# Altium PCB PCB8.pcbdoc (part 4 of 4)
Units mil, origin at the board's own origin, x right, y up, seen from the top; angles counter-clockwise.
Board outline 6799.06 x 5716.8 mil, 2 copper layers (Top Layer, Bottom Layer); 312 components, 374 nets, 1333 pads, 994 vias.
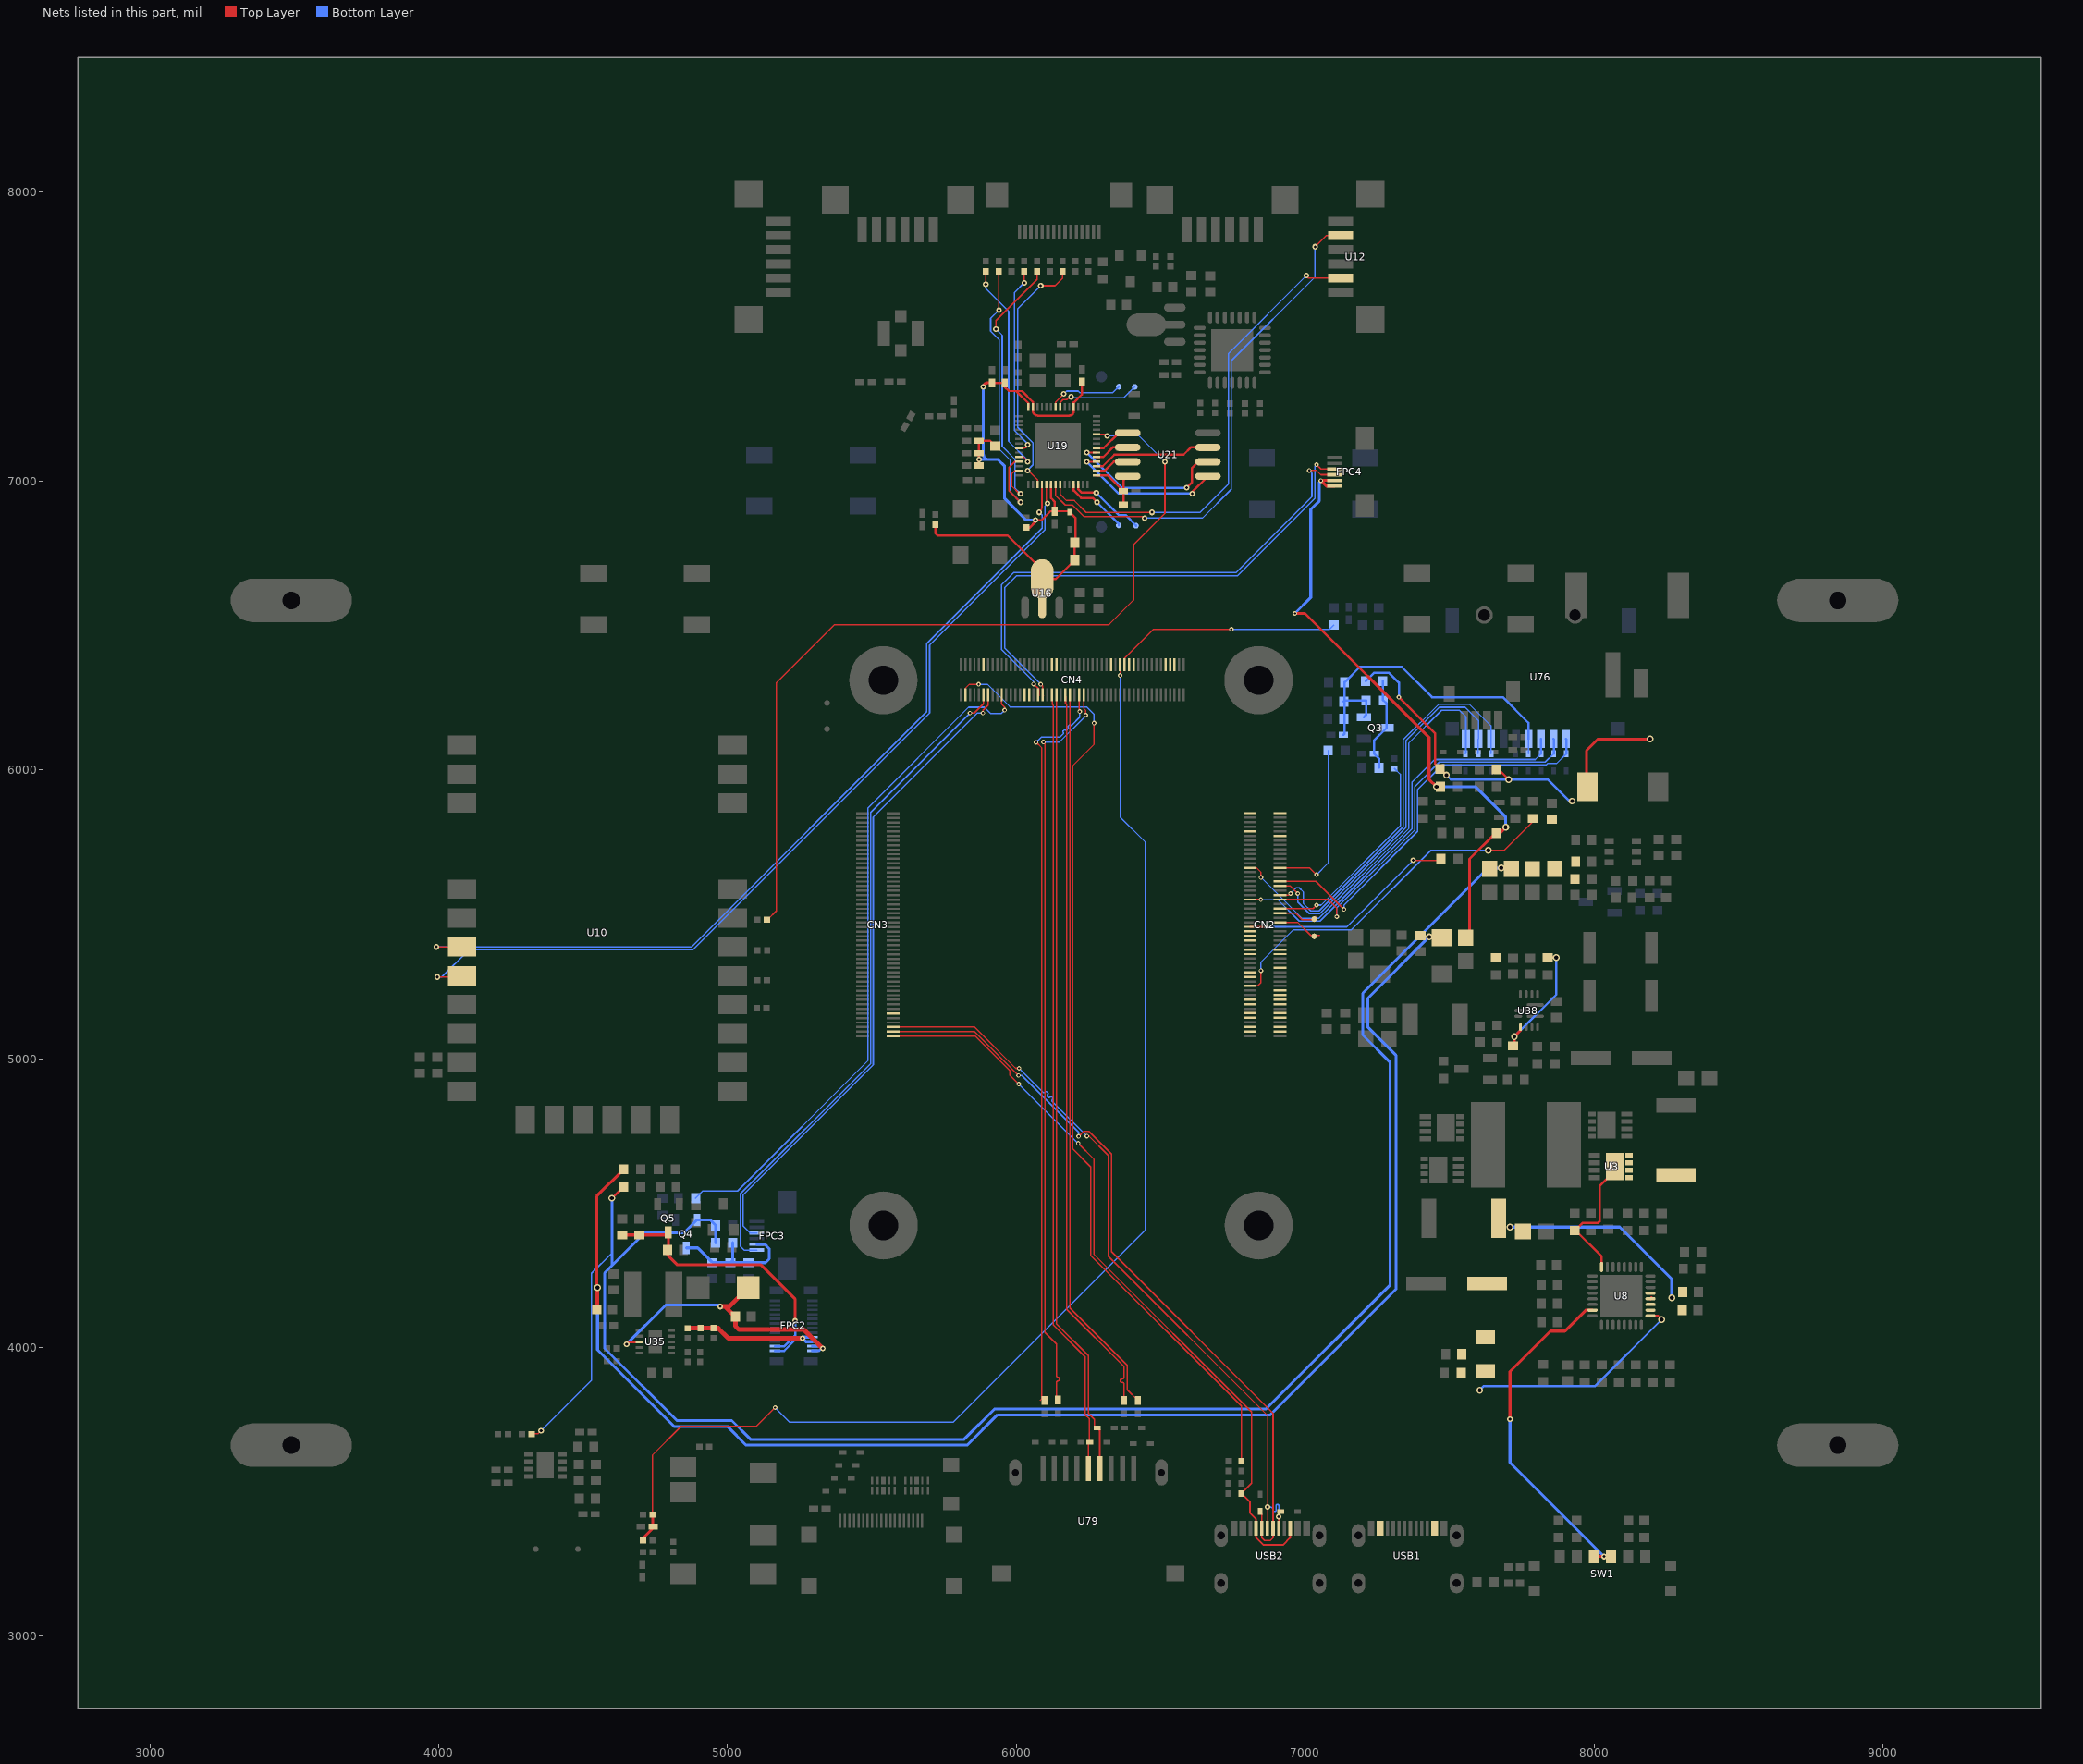
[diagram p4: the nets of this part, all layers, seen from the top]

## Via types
v1: diameter 19.7, hole 9.84, Top Layer to Bottom Layer, 526 vias
v2: diameter 15.75, hole 7.87, Top Layer to Bottom Layer, 322 vias
v3: diameter 19.68, hole 9.84, Top Layer to Bottom Layer, 98 vias
v4: diameter 23.62, hole 13.78, Top Layer to Bottom Layer, 39 vias
v5: diameter 24, hole 12, Top Layer to Bottom Layer, 9 vias

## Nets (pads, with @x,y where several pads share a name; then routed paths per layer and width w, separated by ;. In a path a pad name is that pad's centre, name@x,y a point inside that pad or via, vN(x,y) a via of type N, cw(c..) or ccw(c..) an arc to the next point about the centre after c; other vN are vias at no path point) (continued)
PCON: R8.2 R375.1 U3.5 U3.6 U3.7 U3.8 U8.16 | length 475.5
  Top Layer w7.87: R8.2@7933.02,4405.21 R8.2@7935.75,4405.21 ; U8.16@8026.6,4278.49 8026.6,4314.37 R8.2@7935.75,4405.21 ; U3.8@8072.36,4626.32 8072.36,4611.16 8019.47,4558.27 8019.47,4436.49 8014.47,4431.49 7962.03,4431.49 R8.2@7935.75,4405.21
PHY1_LED0_Y1: CN2.19
PHY1_LED1_G: CN2.17
PHY1_LED2_Y: CN2.15
PHY1_MDI0+: CN2.12
PHY1_MDI0-: CN2.10
PHY1_MDI1+: CN2.4
PHY1_MDI1-: CN2.6
PHY1_MDI2+: CN2.11
PHY1_MDI2-: CN2.9
PHY1_MDI3+: CN2.3
PHY1_MDI3-: CN2.5
PI_NLED_ACTIVITY: CN2.21
PMIC_RESET_KEY: CN2.100
PMW0_M0: CN2.48
PMW0_M1: CN2.50 R106.2 | length 758.5
  Top Layer w5: CN2.50@6808.76,5456.26 v2(6864.47,5456.26) ; v3(7374.47,5686.49) 7464.81,5686.49 R106.2@7469.81,5691.49
  Bottom Layer w5: v2(6864.47,5456.26) 7144.23,5456.26 v3(7374.47,5686.49)
PMW4: CN2.46
PWM3_IR: CN2.24 R97.2 | length 1245.8
  Top Layer w5: CN2.24@6820.57,5252.25 6836.48,5252.25 6847.22,5262.99 v2(6847.22,5304.33) ; v4@7644.47,5721.49 7689.47,5721.49 7787.76,5819.78 R97.2@7787.76,5831.54
  Bottom Layer w5: v2(6847.22,5304.33) 6847.22,5334.24 6958.19,5445.21 7159.13,5445.21 7435.41,5721.49 v4(7634.47,5721.49)
PWM11: CN2.31
PWRON_KEY: CN2.99
RBAT: SW1.3 SW1.4 U8.23 | length 1208.5
  Top Layer w10: v1(7709.47,3751.49) 7709.47,3916.49 7849.47,4056.49 7899.47,4056.49 7971.87,4128.89 U8.23@7995.1,4128.89 ; SW1.3@7999.94,3275.55 v1(8035.08,3275.55) SW1.4@8059,3275.55
  Bottom Layer w10: v1(7709.47,3751.49) 7709.47,3601.16 v1(8035.08,3275.55)
RST1: R36.2 U19.13 | length 978.1
  Top Layer w5: v3(5929.47,7526.49) 5929.47,7555.55 6071.73,7697.81 R36.2@6071.73,7726.46 ; U19.13@6009.66,7035.53 5994.07,7035.53 5984.47,7025.93 5984.47,6981.49 6009.47,6956.49 v3(6014.47,6956.49)
  Bottom Layer w5: v3(5929.47,7526.49) 5951.14,7504.82 5951.14,7119.82 5994.47,7076.49 5994.47,6976.49 v3(6014.47,6956.49)
RUN_PG: CN2.92
RX: U12.2 U19.22 | length 1640.6
  Top Layer w5: U19.22@6151.69,6987.99 6151.69,6954.27 6173.72,6932.24 6200.76,6932.24 6241.51,6891.49 v3(6469.47,6891.49) ; v3(7004.47,7711.49) ccw(c7013.29,7711.49) 7013.29,7702.67 U12.2@7123.29,7702.67
  Bottom Layer w5: v3(6469.47,6891.49) 6636.18,6891.49 6734.47,6989.78 6734.47,7441.49 v3(7004.47,7711.49)
RXEN: U10.6 U19.18 | length 3064.2
  Top Layer w5: v3(3992.29,5386.75) 4056.56,5386.75 ccw(c4056.56,5390.37) U10.6@4060.18,5390.37 ; v3(6079.47,6891.49) ccw(c6060.26,6914.06) 6088.7,6905.72 U19.18@6088.7,6987.99
  Bottom Layer w5: v3(3992.29,5386.75) 4875.22,5386.75 5689.47,6200.99 5689.47,6436.49 6089.47,6836.49 6089.47,6881.49 v3(6079.47,6891.49)
RY: U12.5 U19.21 | length 1785.5
  Top Layer w5: U19.21@6135.94,6987.99 6135.94,6950.02 6169.47,6916.49 6194.5,6916.49 6234.2,6876.79 6439.17,6876.79 v3(6444.47,6871.49) ; v3(7034.47,7811.49) 7073.28,7850.31 U12.5@7123.29,7850.31
  Bottom Layer w5: v3(6444.47,6871.49) 6644.47,6871.49 6744.47,6971.49 6744.47,7416.49 7034.47,7706.49 v3(7034.47,7811.49)
SARADC_IN3: CN2.37
SARADC_VIN0_KEY/RECOVERY: CN4.26
SARADC_VIN1_HW_ID: CN4.28 R100.2 | length 797.1
  Top Layer w5: CN4.28@6374.47,6361.92 CN4.28@6374.47,6363.3 ; CN4.28@6374.7,6363.54 CN4.28@6374.47,6363.3 ; v2(6744.47,6486.49) 6474.47,6486.49 6374.47,6386.49 CN4.28@6374.47,6363.3
  Bottom Layer w5: v2(6744.47,6486.49) 7084.37,6486.49 R100.2@7099.14,6501.27
SARADC_VIN2_HP_HOOK: C46.2 CN4.30 R54.2 R56.2 | length 4374.3
  Top Layer w5: R56.2@4739.47,3421.49 4739.47,3626.49 4839.47,3726.49 5099.47,3726.49 v2(5164.47,3791.49) ; CN4.30@6358.96,6363.54 6359.47,6363.03 v2(6359.47,6326.49)
  Top Layer w10: R54.2@4707.43,3331.49 4707.43,3339.45 4741.51,3373.53 R56.2@4741.51,3421.49
  Bottom Layer w5: v2(5164.47,3791.49) 5214.47,3741.49 5781.45,3741.49 6446.91,4406.94 6446.91,5749.06 6359.47,5836.49 v2(6359.47,6326.49)
SCK: R27.2 U19.38 | length 2989.9
  Top Layer w5: R27.2@5136.51,5481.49 5139.47,5481.49 5169.47,5511.49 5169.47,6301.49 5370.96,6502.98 6320.96,6502.98 6405.58,6587.6 6405.58,6779 6514.47,6887.89 v3(6514.47,7066.49) ; U19.38@6277.97,7161.52 6309.44,7161.52 v3(6314.47,7156.49)
  Bottom Layer w5: v3(6314.47,7156.49) 6424.47,7156.49 v3(6514.47,7066.49)
SCL: R30.2 U19.10 | length 757.6
  Top Layer w5: v3(5894.23,7681.49) R30.2@5894.23,7726.46 ; U19.10@6009.66,7082.78 6025.94,7082.78 6038.65,7070.08 v3(6038.65,7066.49)
  Bottom Layer w5: v3(5894.23,7681.49) 5894.23,7666.73 5973.51,7587.45 5973.51,7137.12 6038.65,7071.99 v3(6038.65,7066.49)
SCLK1: R39.2 U19.17 | length 878.4
  Top Layer w5: v3(6038.55,7036.49) 6041.54,7036.49 6072.95,7005.08 U19.17@6072.95,6987.99 ; v3(6084.47,7676.49) 6134.47,7676.49 6160.48,7702.5 R39.2@6160.48,7726.46
  Bottom Layer w5: v3(6038.55,7036.49) 6057.81,7055.76 6057.81,7132.35 6004.56,7185.6 6004.56,7596.59 v3(6084.47,7676.49)
SDA: R31.2 U19.11 | length 1035.1
  Top Layer w5: R31.2@5938.6,7726.46 5939.47,7725.59 v3(5939.47,7591.49) ; U19.11@6009.66,7067.03 5995.01,7067.03 5974.47,7046.49 5974.47,6966.49 v3(6014.47,6926.49)
  Bottom Layer w5: v3(5939.47,7591.49) 5911.13,7563.15 5911.13,7518.89 5940,7490.03 5940,7110.97 5979.47,7071.49 5979.47,6961.49 v3(6014.47,6926.49)
SDMMC0_CLK: CN2.57 R59.1 | length 741.6
  Top Layer w5: CN2.57@6913.48,5519.25 7027.22,5519.25 v2(7039.47,5531.49)
  Bottom Layer w5: v2(7039.47,5531.49) 7055.21,5531.49 7329.47,5805.75 7329.47,5984.45 R59.1@7309.47,6004.45
SDMMC0_CMD: CN2.62 D22.2 U76.3 | length 1424.8
  Top Layer w5: CN2.62@6808.76,5550.74 6846.42,5550.74 v2(6846.59,5550.58)
  Bottom Layer w5: v2(6846.59,5550.58) 6905.39,5550.58 6979.47,5476.49 7051.32,5476.49 7369.47,5794.64 7369.47,5956.49 7448.68,6035.71 7796.66,6035.71 D22.2@7816.97,6056.02
  Bottom Layer w8: U76.3@7816.43,6106.77 7816.43,6056.55 D22.2@7816.97,6056.02
SDMMC0_D0: CN2.63 D19.2 U76.7 | length 1397
  Top Layer w5: CN2.63@6913.48,5566.49 6944.47,5566.49 v2(6949.47,5571.49)
  Bottom Layer w5: v2(6949.47,5571.49) 6969.47,5591.49 6979.47,5591.49 6994.47,5576.49 6994.47,5536.49 7019.47,5511.49 7047.94,5511.49 7339.47,5803.02 7339.47,6104.22 7461.74,6226.49 7569.47,6226.49 7643.21,6152.75 U76.7@7643.21,6106.77 7644.47,6105.51 D19.2@7644.47,6056.02
SDMMC0_D1: CN2.67 D18.2 U76.8 | length 1350.6
  Top Layer w5: CN2.67@6913.48,5597.99 6947.97,5597.99 v2(6974.47,5571.49)
  Bottom Layer w5: v2(6974.47,5571.49) 6974.47,5541.49 7014.47,5501.49 7050.67,5501.49 7349.47,5800.29 7349.47,6101.49 7464.47,6216.49 7554.47,6216.49 7599.89,6171.07 U76.8@7599.89,6106.77 7599.47,6106.34 D18.2@7599.47,6056.02
SDMMC0_D2/ARMJTAG_TCK: CN2.69 D24.2 U76.1 | length 1400
  Top Layer w5: CN2.69@6913.48,5613.74 7037.22,5613.74 v2(7134.47,5516.49)
  Bottom Layer w5: v2(7134.47,5516.49) 7134.47,5531.49 7389.47,5786.49 7389.47,5931.49 7475.45,6017.48 7819.04,6017.48 7819.25,6017.26 7819.47,6017.48 7834.93,6017.48 7838.94,6021.49 7869.94,6021.49 D24.2@7904.47,6056.02
  Bottom Layer w8: U76.1@7903.04,6106.77 7904.47,6105.34 D24.2@7904.47,6056.02
SDMMC0_D3/ARMJTAG_TMS: CN2.61 D23.2 U76.2 | length 1379.8
  Top Layer w5: CN2.61@6913.48,5550.74 7080.22,5550.74 7109.47,5521.49 v2(7109.47,5491.49)
  Bottom Layer w5: v2(7109.47,5491.49) 7109.47,5521.49 7380.33,5792.35 7380.33,5942.35 7464.47,6026.49 7831.19,6026.49 D23.2@7860.72,6056.02
  Bottom Layer w8: U76.2@7859.74,6106.77 7860.72,6105.79 D23.2@7860.72,6056.02
SDMMC0_DET_L: CN2.76 D17.2 U76.CD | length 1440.6
  Top Layer w5: CN2.76@6808.76,5660.98 6831.41,5660.98 6847.14,5645.25 v2(6847.14,5627.28)
  Bottom Layer w5: v2(6847.14,5627.28) 6987.92,5486.49 7048.6,5486.49 7359.47,5797.37 7359.47,6093.21 7472.75,6206.49 7534.47,6206.49 7556.59,6184.37 U76.CD@7556.59,6106.77 7556.59,6058.14 D17.2@7554.47,6056.02
SDMMC_PWREN: CN2.75 R63.1 | length 582.8
  Top Layer w5: CN2.75@6913.48,5660.98 7014.98,5660.98 v2(7039.47,5636.49)
  Bottom Layer w5: v2(7039.47,5636.49) 7079.81,5676.83 R63.1@7079.81,6066.49
SPI0_CSO_MO: CN2.28
SPI0_MISO_MO: CN2.30
SPI3_CLK_M0: CN2.38
SPI3_CSO_M0: CN2.39
SPI3_MISO_M0: CN2.40
SPI3_MOSI_M0: CN2.44
SPICLK: U19.33 U21.6 | length 122.7
  Top Layer w7.87: U19.33@6277.97,7082.78 6300.76,7082.78 6335.42,7117.44 U21.6@6386.29,7117.44
SPICS0: U19.32 U21.1 | length 527.9
  Top Layer w7.9: v3(6244.47,7066.49) 6277.43,7066.49 U19.32@6277.97,7067.03 ; v3(6609.47,6956.49) 6609.47,6962.67 U21.1@6664.25,7017.44
  Bottom Layer w7.9: v3(6244.47,7066.49) 6354.47,6956.49 v3(6609.47,6956.49)
SPID: U19.35 U21.5 | length 130.3
  Top Layer w7.87: U19.35@6277.97,7114.27 6302.25,7114.27 6355.42,7167.44 U21.5@6386.29,7167.44
SPIHD: U19.30 U21.7 | length 121.5
  Top Layer w7.87: U19.30@6277.97,7035.53 6306.15,7035.53 6338.06,7067.44 U21.7@6386.29,7067.44
SPIQ: U19.34 U21.2 | length 570.8
  Top Layer w7.9: v3(6244.47,7098.53) U19.34@6277.97,7098.53 ; v3(6589.47,6976.49) 6608.51,6995.54 6608.51,7045.54 6630.42,7067.44 U21.2@6664.25,7067.44
  Bottom Layer w7.9: v3(6244.47,7098.53) 6366.51,6976.49 v3(6589.47,6976.49)
SPIWP: U19.31 U21.3 | length 413.7
  Top Layer w7.87: U19.31@6277.97,7051.28 6299.26,7051.28 6339.47,7091.49 6579.47,7091.49 6604.47,7116.49 6663.29,7116.49 U21.3@6664.25,7117.44
SPKN_OUT: CN4.58
SPKP_OUT: CN4.60
SYNC_IN: CN2.16
SYNC_OUT: CN2.18
TOUCH_RST: R35.2 U19.8 | length 669.3
  Top Layer w5: U19.8@6009.66,7114.27 6027.25,7114.27 ccw(c6027.88,7125.04) v3(6038.65,7125.57) ; v3(6027.35,7686.49) R35.2@6027.35,7726.46
  Bottom Layer w5: v3(6027.35,7686.49) 5993.48,7652.62 5993.48,7175.28 6038.65,7130.11 v3(6038.65,7125.57)
TP_DET_1: CN4.81 R64.2 | length 2350.9
  Top Layer w5: CN4.81@5949.15,6252.44 5949.15,6226.81 5959.47,6216.49 v2(5959.47,6206.49)
  Bottom Layer w5: R64.2@4889.13,4516.49 4914.13,4541.49 5034.47,4541.49 5486.47,4993.49 5486.47,5868.49 5834.47,6216.49 5889.47,6216.49 5910.84,6195.12 5948.09,6195.12 v2(5959.47,6206.49)
TP_INT_1: CN4.87 FPC3.3 | length 2253.3
  Top Layer w5: v2(5884.47,6196.49) 5884.47,6206.49 5901.9,6223.93 CN4.87@5901.9,6252.44
  Bottom Layer w5: FPC3.3@5101.74,4396.26 5077.9,4396.26 5053.47,4420.69 5053.47,4527.76 5504.47,4978.76 5504.47,5836.49 5864.47,6196.49 v2(5884.47,6196.49)
TP_INT_L: CN4.8
TP_PWR_DET: CN4.24
TP_RST_1: CN4.89 FPC3.6 | length 2322.3
  Top Layer w5: v2(5839.47,6196.49) 5854.47,6196.49 5886.16,6228.18 CN4.89@5886.16,6252.44
  Bottom Layer w5: FPC3.6@5101.74,4337.2 5057.44,4337.2 5044.47,4350.17 5044.47,4531.49 5495.47,4982.49 5495.47,5852.49 v2(5839.47,6196.49)
TP_RST_L: CN4.6
TS: CN4.90
TV_OUT: CN3.11
TXEN: U10.7 U19.19 | length 3120.7
  Top Layer w5: v3@3997.48,5282.58 4068.48,5282.58 ccw(c4068.48,5285.17) U10.7@4071.07,5285.17 ; U19.19@6104.45,6987.99 6104.47,6926.39 v3(6108.34,6922.52)
  Bottom Layer w5: v3(3994.89,5282.58) 4010.56,5282.58 4104.47,5376.49 4879.47,5376.49 5699.72,6196.75 5699.72,6432.25 6099.72,6832.25 6099.72,6913.9 v3(6108.34,6922.52)
U0RX: RX.1 U19.50 | length 262
  Top Layer w5: U19.50@6135.94,7256.3 6135.94,7272.96 v3(6164.47,7301.49)
  Bottom Layer w5: v3(6164.47,7301.49) 6174.47,7311.49 6214.47,7311.49 6219.47,7306.49 6334.66,7306.49 RX.1@6354.84,7326.67
U0TX: TX.1 U19.49 | length 298.4
  Top Layer w5: U19.49@6151.69,7256.3 6151.69,7271.63 6161.55,7281.49 6174.47,7281.49 6181.59,7288.62 6186.59,7288.62 v3(6189.47,7291.49)
  Bottom Layer w5: v3(6189.47,7291.49) 6192.34,7288.62 6372.42,7288.62 TX.1@6409.84,7326.04
UART2_RX: CN2.51 TP3.1 | length 159.1
  Top Layer w5: CN2.51@6913.48,5472 6973.96,5472 7019.47,5426.49 TP3.1@7039.48,5426.49 ; TP3.1@7036.48,5423.49 TP3.1@7039.48,5426.49 ; 7049.48,5426.49 TP3.1@7039.48,5426.49
UART2_TX: CN2.55 TP4.1 | length 136.8
  Top Layer w5: CN2.55@6913.48,5503.5 6967.46,5503.5 6989.47,5481.49 7025.11,5481.49 7036.48,5492.86
USB2.0_HUB_PWR: CN4.34
USB2_HOST2_DM: CN4.65 FPC4.3 | length 1829.1
  Top Layer w5: v2(6059.47,6296.93) 6060.88,6296.93 6077.97,6279.84 CN4.65@6077.97,6255.27 ; v2(7014.47,7036.49) 7039.47,7036.49 7054.23,7021.73 FPC4.3@7101.74,7021.73
  Bottom Layer w5: v2(6059.47,6296.93) 6059.47,6305.94 5948.48,6416.92 5948.48,6640.51 5990.47,6682.49 6760.47,6682.49 7023.47,6945.49 7023.47,7027.49 v2(7014.47,7036.49)
USB2_HOST2_DP: CN4.63 FPC4.4 | length 1821.1
  Top Layer w5: v2(6084.47,6296.49) 6091.35,6289.61 6091.35,6257.64 CN4.63@6093.72,6255.27 ; v2(7039.47,7056.49) 7054.54,7041.42 FPC4.4@7101.74,7041.42
  Bottom Layer w5: v2(6084.47,6296.49) 5959.47,6421.49 5959.47,6631.49 5999.47,6671.49 6765,6671.49 7034.45,6940.94 7034.45,7051.48 v2(7039.47,7056.49)
USB2_HOST3_DM: CN4.71
USB2_HOST3_DP: CN4.69
USB3_HOST1_DM: CN4.47 L6.1 | length 2569.8
  Top Layer w5: v2(6068.47,6095.4) 6088.47,6075.41 6088.47,3822.18 6083.07,3816.78 ; CN4.47@6217.22,6259.6 6217.22,6203.74 v2(6219.47,6201.49)
  Bottom Layer w5: v2(6068.47,6095.4) 6085.93,6112.87 6150.29,6112.87 6162.27,6124.85 ccw(c6159.91,6127.21) 6162.27,6129.57 cw(c6164.63,6131.93) 6162.27,6134.29 6166.03,6138.05 cw(c6168.39,6135.69) 6170.75,6138.05 ccw(c6173.11,6140.42) 6175.47,6138.05 6179.24,6141.82 ccw(c6176.88,6144.18) 6179.24,6146.54 cw(c6181.6,6148.9) 6179.24,6151.26 6183,6155.02 cw(c6185.36,6152.66) 6187.72,6155.02 ; 6187.72,6155.03 ccw(c6190.08,6157.39) 6192.45,6155.03 ; 6192.45,6155.02 6219.47,6182.05 v2(6219.47,6201.49)
USB3_HOST1_DP: CN4.45 L7.1 | length 2568.4
  Top Layer w5: v2(6093.86,6096.3) 6099.47,6090.69 6099.47,4051.54 6139.47,4011.54 6139.47,3901.25 ccw(c6144.47,3901.25) 6144.47,3896.25 cw(c6144.47,3891.25) 6149.47,3891.25 6149.47,3889.25 cw(c6144.47,3889.25) 6144.47,3884.25 ccw(c6144.47,3879.25) 6139.47,3879.25 L7.1@6139.47,3817.95 ; CN4.45@6232.97,6259.6 6232.97,6212.99 6240.52,6205.44 v2(6240.52,6189.33)
  Bottom Layer w5: v2(6093.86,6096.3) 6149.53,6096.3 6240.52,6187.28 v2(6240.52,6189.33)
USB3_HOST1_SSRXN: CN4.59 D8.2 U79.5 | length 2734.1
  Top Layer w5: CN4.59@6125.19,6255.25 6125.19,6225.77 6128.47,6222.49 6128.47,4076.94 6238.47,3966.94 6238.47,3847.94 ; 6238.06,3848.35 6238.47,3847.94 ; U79.5@6249.47,3581.1 6249.47,3666.02 D8.2@6254.47,3671.02 ; D8.2@6253.47,3672.13 D8.2@6253.47,3672.97 ; D8.2@6254.94,3671.49 D8.2@6253.47,3672.97 ; D8.2@6255.26,3671.49 D8.2@6253.47,3673.28 ; 6238.47,3847.94 6238.47,3766.94 6253.47,3751.94 D8.2@6253.47,3673.28 ; D8.2@6253.47,3672.97 D8.2@6253.47,3673.28
  Top Layer w7.87: D8.2@6254.47,3671.02 D8.2@6254.94,3671.49
USB3_HOST1_SSRXP: CN4.57 D9.2 U79.6 | length 2733.2
  Top Layer w5: CN4.57@6139.47,6255.27 6139.47,4081.49 6249.47,3971.49 6249.47,3771.49 6270.28,3750.68 D9.2@6270.28,3721.16 ; D9.2@6280.28,3720.33 D9.2@6280.28,3721.16 ; U79.6@6288.84,3581.1 6288.84,3712.6
  Top Layer w7.87: D9.2@6279.94,3721.49 6280.28,3721.16 6288.84,3712.6
USB3_HOST1_SSTXN: C49.1 CN4.53 | length 2536.8
  Top Layer w5: CN4.53@6171.15,6253.4 6170.37,6252.61 6170.37,6230.6 6174.73,6226.23 6174.73,4131.57 6372.65,3933.65 6372.65,3896.83 cw(c6366.65,3896.83) 6366.65,3890.83 6365.47,3890.83 ccw(c6365.47,3884.83) 6365.47,3878.83 6366.65,3878.83 cw(c6366.65,3872.83) 6372.65,3872.83 C49.1@6372.65,3816.78
USB3_HOST1_SSTXP: C50.1 CN4.51 | length 2540
  Top Layer w5: CN4.51@6185.73,6259.6 6185.73,4136.13 6383.65,3938.21 6383.65,3853.49 C50.1@6420.36,3816.78
USB_D+: D+.1 U19.26 | length 269.1
  Top Layer w7.87: U19.26@6214.68,6987.99 6214.68,6970.96 6225.93,6959.72 v3(6276.96,6959.72)
  Bottom Layer w7.87: v3(6276.96,6959.72) 6355.65,6881.04 6379.44,6881.04 6414.21,6846.26 D+.1@6414.21,6845.41
USB_D-: D-.1 U19.25 | length 229.4
  Top Layer w7.87: U19.25@6198.94,6987.99 6198.94,6967.02 6224.47,6941.49 6264.47,6941.49 v3(6279.47,6926.49)
  Bottom Layer w7.87: v3(6279.47,6926.49) 6354.47,6851.49 D-.1@6354.47,6846.49
USB_OTG0_DM: CN3.3 D5.2 USB2.A7 USB2.B7 | length 2655.1
  Top Layer w5: CN3.3@5572.93,5093.66 5855.03,5093.66 v2(6007.2,4941.49) ; v2(6215.74,4730.59) 6233.01,4747.87 6251.25,4747.87 6329.47,4669.65 6329.47,4331.49 6889.11,3771.86 USB2.A7@6889.11,3373.98 6889.11,3341.13 6879.47,3331.49 6859.47,3331.49 6849.74,3341.23 USB2.B7@6849.74,3373.98 6849.74,3425.75 D5.2@6843.99,3431.49
  Bottom Layer w5: v2(6007.2,4941.49) 6018.91,4941.49 6215.74,4744.66 v2(6215.74,4730.59)
USB_OTG0_DP: CN3.5 D4.2 USB2.A6 USB2.B6 | length 2648.8
  Top Layer w5: CN3.5@5572.93,5109.41 5854.84,5109.41 5997.75,4966.49 v2(6009.47,4966.49) ; v2(6244.47,4731.49) 6252.07,4731.49 6318.47,4665.09 6318.47,4315.5 6870.02,3763.95 v3(6870.02,3447.76) 6870.02,3374.57 USB2.A6@6869.43,3373.98 ; USB2.B6@6908.8,3373.98 v3(6908.75,3413.27) 6908.8,3430.34 D4.2@6914.94,3436.49
  Bottom Layer w5: v2(6009.47,4966.49) 6092.16,4883.8 ccw(c6095.91,4887.55) 6099.66,4883.8 cw(c6103.41,4880.05) 6107.16,4883.8 6108.15,4882.81 cw(c6104.4,4879.06) 6108.15,4875.31 ccw(c6111.9,4871.56) 6108.15,4867.81 6109.13,4866.83 ccw(c6112.88,4870.58) 6116.63,4866.83 cw(c6120.38,4863.08) 6124.13,4866.83 6125.12,4865.84 cw(c6121.37,4862.09) 6125.12,4858.34 ccw(c6128.87,4854.59) 6125.12,4850.84 v2(6244.47,4731.49) ; v3(6870.02,3447.76) 6878.2,3447.76 cw(c6878.2,3436.49) 6889.47,3436.49 ccw(c6894.47,3436.49) 6894.47,3431.49 ccw(c6894.47,3436.49) 6899.47,3436.49 6899.47,3451.49 cw(c6904.47,3451.49) 6904.47,3456.49 cw(c6904.47,3452.21) 6908.75,3452.21 v3(6908.75,3413.27)
USB_OTG0_ID: CN3.1 R53.1 USB2.A5 USB2.B5 | length 2626.3
  Top Layer w5: CN3.1@5572.93,5077.91 5858.05,5077.91 5977.69,4958.27 5977.69,4942.09 v2(6008.03,4911.75) ; v2(6214.47,4706.49) 6269.47,4651.49 6269.47,4321.49 6814.47,3776.49 6814.47,3529.45 R53.1@6779.47,3494.45
  Top Layer w6: R53.1@6779.47,3494.45 6809.47,3464.45 6809.47,3426.49 6829.47,3406.49 6829.47,3374.56 USB2.A5@6830.06,3373.98 6830.06,3340.91 6854.47,3316.49 6924.47,3316.49 6948.17,3340.19 USB2.B5@6948.17,3373.98
  Bottom Layer w5: v2(6008.03,4911.75) 6213.29,4706.49 v2(6214.47,4706.49)
USB_OTG0_VBUSDET: CN4.97 R49.1 | length 3387.3
  Top Layer w5: CN4.97@5824.28,6248.62 5824.28,6256.99 5823.16,6258.11 5823.16,6282.34 5837.31,6296.49 v2(5869.47,6296.49) ; v2(6269.47,6161.49) 6269.47,6088.51 6195.63,6014.67 6195.63,4686.93 6257.93,4624.63 6257.93,4318.43 6779.47,3796.89 R49.1@6779.47,3606.42
  Bottom Layer w5: v2(5869.47,6296.49) 5899.47,6296.49 5978.09,6217.87 6243.09,6217.87 6269.47,6191.49 v2(6269.47,6161.49)
USB_PWR_H: CN4.10
VBUS: C2.2 R1.1 R6.2 U8.1 USB1.A4 USB1.A9 USB1.B4 USB1.B9 | length 775.3
  Top Layer w7.87: U8.1@8195.9,4109.19 8221.77,4109.19 v4(8234.47,4096.49)
  Bottom Layer w7.87: v4(7604.47,3851.49) 7619.47,3866.49 8004.47,3866.49 v4(8234.47,4096.49)
VBUSI: C3.2 C8.1 C10.1 R1.2 R374.1 U7.1 U8.3 U8.4 U8.5 | length 709.1
  Top Layer w10: U8.4@8195.9,4168.29 U8.4@8199.09,4171.49
  Bottom Layer w10: v4(7709.47,4416.49) 8089.47,4416.49 8269.47,4236.49 v4@8269.47,4166.49
  other v4: 8269.47,4171.49
VBYSG: U8.2
VCC: C91.2 R93.1 U38.9 | length 443
  Top Layer w8: R93.1@7839.77,5349.36 v4(7869.47,5349.36)
  Top Layer w10: C91.2@7724.43,5037.6 7724.43,5076.46 7745.79,5097.82 U38.9@7745.79,5109.16
  Bottom Layer w8: v4(7724.47,5076.49) 7869.47,5221.49 v4(7869.47,5349.36)
VCC3V3_SD_1: C55.2 C56.2 C58.2 C59.2 D21.2 Q3.2 R58.1 U76.4 | length 1170.5
  Bottom Layer w5: U76.4@7773.12,6106.77 7773.22,6106.67 D21.2@7773.22,6056.02
  Bottom Layer w8: C59.2@7132.29,6120.8 7136.53,6125.03 C55.2@7136.53,6239.14 ; C55.2@7133.59,6236.21 C55.2@7136.53,6239.14 ; Q3.2@7203.48,6182.66 7211.42,6190.6 R58.1@7211.42,6240.28 7137.66,6240.28 C55.2@7136.53,6239.14 ; U76.4@7773.12,6106.77 7773.12,6162.84 7684.47,6251.49 7439.47,6251.49 7334.47,6356.49 7189.49,6356.49 C58.2@7136.53,6303.53 C55.2@7136.53,6239.14
VCC3V3_SYS: C77.1 C82.2 C408.2 C409.2 C410.2 C411.2 Q4.2 R60.1 R62.2 R65.2 R69.1 R86.2 R96.1 R105.1 R383.1 U37.2 | length 8036.6
  Top Layer w5: R383.1@4321.51,3701.49 4344.47,3701.49 v1(4354.47,3711.49)
  Top Layer w8: v2(7324.47,6251.49) 7449.47,6126.49 7449.47,6021.16 R105.1@7467.24,6003.39 7489.14,5981.49 v4(7489.47,5981.49) ; R96.1@7662.42,6001.2 7669.76,6001.2 v4(7704.47,5966.49)
  Top Layer w10: v4(4599.47,4516.49) 4600.04,4516.49 R69.1@4640.35,4556.8 ; U37.2@7977.43,5941.49 7974.47,5944.45 7974.47,6066.49 8014.47,6106.49 v4(8194.47,6106.49)
  Bottom Layer w5: v1(4354.47,3711.49) 4529.16,3886.18 4529.16,4256.18 4599.47,4326.49
  Bottom Layer w8: R60.1@7209.81,6306.49 7239.81,6336.49 7289.47,6336.49 7324.47,6301.49 v2(7324.47,6251.49) ; v4(7489.47,5981.49) 7504.47,5966.49 v4(7704.47,5966.49) 7839.47,5966.49 7914.47,5891.49 v4(7924.47,5891.49)
  Bottom Layer w10: v4(4599.47,4516.49) 4599.47,4326.49 4599.47,4282.91 ; R62.2@4958.93,4362.31 R65.2@4958.93,4422.31 4939.5,4441.73 Q4.2@4894.6,4441.73 4849.36,4396.49 4713.05,4396.49 4599.47,4282.91 ; v4(7678.89,5660.04) 7633.53,5660.04 7199.47,5225.98 7199.47,5081.49 7294.47,4986.49 7294.47,4216.49 6864.47,3786.49 5924.47,3786.49 5819.47,3681.49 5079.47,3681.49 5014.47,3746.49 4824.47,3746.49 4574.47,3996.49 4574.47,4257.91 4599.47,4282.91
VCC5V0_USB: C83.2 C406.1 FPC4.1 FPC4.2 L8.1 L10.2 R70.2 R95.1 R104.1 | length 7494.7
  Top Layer w10: v4(4549.47,4206.49) 4549.47,4134.05 L8.1@4546.91,4131.49 4546.91,4523.37 R70.2@4640.35,4616.8 ; v2(6964.47,6541.49) 6999.67,6541.49 7429.47,6111.69 7429.47,5966.49 v4(7454.47,5941.49) 7467.8,5941.49 R104.1@7468.1,5941.2 ; FPC4.1@7101.74,6982.36 7073.6,6982.36 v2(7054.47,7001.49) 7055.03,7002.05 FPC4.2@7101.74,7002.05 ; C406.1@7556.27,5417.66 7569.47,5430.86 7569.47,5691.49 7658.83,5780.86 R95.1@7662.08,5780.86 7673.83,5780.86 v4(7694.47,5801.49)
  Bottom Layer w10: v4(4549.47,4206.49) 4549.47,3991.49 4814.47,3726.49 4999.47,3726.49 5064.47,3661.49 5829.47,3661.49 5934.47,3766.49 6879.47,3766.49 7314.47,4201.49 7314.47,5011.49 7216.66,5109.3 7216.66,5208.17 v4(7429.81,5421.32) ; v2(6964.47,6541.49) 7019.47,6596.49 7019.47,6901.49 7049.47,6931.49 7049.47,6996.49 v2(7054.47,7001.49) ; v4(7454.47,5941.49) 7589.47,5941.49 7694.47,5836.49 v4(7694.47,5801.49)
VCC_LCD_MIPI: C62.2 C63.2 C64.2 FPC2.1 FPC2.2 Q5.3 | length 1060.8
  Top Layer w10: C63.2@4635.01,4389.24 C62.2@4695.01,4389.24 4786.07,4389.24 Q5.3@4795.01,4398.18 4795.01,4339.36 C64.2@4792.45,4336.8 4792.45,4318.51 4824.47,4286.49 5114.47,4286.49 5234.47,4166.49 v3(5234.47,4091.49)
  Bottom Layer w7.87: FPC2.1@5164.47,3988.26 5196.24,3988.26 5234.47,4026.49 5234.47,4041.49 ; FPC2.2@5164.47,4004.01 5196.99,4004.01 5234.47,4041.49 ; v3(5234.47,4091.49) 5234.47,4041.49
VCC_LDO5V: R101.1
VCC_LEDA1: C72.2 D26.1 FPC2.23 FPC2.24 U35.8 | length 1048
  Top Layer w10: v1(4650.41,4011.2) 4658.31,4019.11 U35.8@4694.53,4019.11
  Top Layer w15.75: v1(4974.47,4141.49) 4991.91,4141.49 ; D26.1@5071.08,4206.49 5006.08,4141.49 4991.91,4141.49 ; v3(5329.47,3996.49) 5264.47,4061.49 5039.47,4061.49 5026.91,4074.05 C72.2@5026.91,4106.49 4991.91,4141.49
  Bottom Layer w10: v1(4650.41,4011.2) 4785.7,4146.49 4969.47,4146.49 v1(4974.47,4141.49) ; FPC2.24@5293.6,3988.26 5316.24,3988.26 5324.47,3996.49 v3(5329.47,3996.49) 5321.95,4004.01 FPC2.23@5293.6,4004.01
VCC_LEDK1: FPC2.21 FPC2.22 R378.2 R379.2 R380.1 | length 487.2
  Top Layer w15.75: R380.1@4861.57,4066.09 4861.77,4066.3 R378.2@4906.7,4066.28 R379.2@4952.22,4066.3 4967.85,4066.3 5002.66,4031.49 v3(5259.47,4031.49)
  Bottom Layer w10: FPC2.22@5293.6,4019.76 5271.2,4019.76 v3(5259.47,4031.49) 5263.48,4035.51 FPC2.21@5293.6,4035.51
VCC_TP: C52.2 C53.2 C54.2 FPC3.5 Q4.3 R62.1 | length 470.3
  Bottom Layer w10: Q4.3@4857.2,4344.48 4896.59,4344.48 C53.2@4947.72,4293.35 C54.2@5010.31,4293.35 ; R62.1@5018.25,4362.31 5018.25,4301.28 C54.2@5010.31,4293.35 ; FPC3.5@5101.74,4356.89 5129.1,4356.89 5144.47,4341.51 5144.47,4306.49 5131.33,4293.35 C52.2@5072.91,4293.35 C54.2@5010.31,4293.35
VCCIO_SD: C57.2 Q3.3 R58.2 R60.2 R61.2 | length 329.6
  Bottom Layer w8: R61.2@7255.91,6006.99 7255.91,6038.66 C57.2@7239.31,6055.26 7239.31,6102.35 Q3.3@7282.22,6145.26 7282.22,6228.8 R58.2@7270.74,6240.28 7269.13,6241.89 R60.2@7269.13,6306.49
VDD3V3: C17.2 C18.2 C27.2 C38.2 C39.2 C41.2 C42.2 C43.2 C398.2 D3.2 L3.2 R40.2 R388.2 U16.2 U19.20 U19.46 U19.55 U19.56 | length 2428.1
  Top Layer w7.87: R40.2@5719.47,6852.33 5719.47,6819.37 5727.34,6811.49 5969.47,6811.49 6089.47,6691.49 U16.2@6089.47,6660.69 6136.11,6660.69 C18.2@6201.91,6726.49 C17.2@6201.91,6786.49 6204.47,6789.05 6204.47,6872.77 D3.2@6185.27,6891.97 6181.97,6895.27 C398.2@6132.18,6895.27 ; C43.2@5870.73,7053.81 v3(5870.73,7074.18) C42.2@5870.73,7096.65 C41.2@5870.73,7139.5 5908.94,7139.5 L3.2@5927.18,7121.25 ; C39.2@5916.02,7339.77 C38.2@5959.6,7339.77 5959.6,7326.36 5974.47,7311.49 5999.47,7311.49 ; U19.56@6041.46,7256.3 6041.46,7269.5 5999.47,7311.49 ; v3(6066.01,6864.76) 6087.74,6864.76 6118.24,6895.27 C398.2@6132.18,6895.27 ; U19.20@6120.2,6987.99 6120.2,6940.76 6132.18,6928.78 C398.2@6132.18,6895.27 ; C27.2@6227.18,7342.35 6227.18,7299.89 6198.94,7271.64 U19.46@6198.94,7256.3 6198.94,7241.83 cw(c6183.6,7241.83) 6183.6,7226.49 6074.47,7226.49 cw(c6074.47,7243.76) 6057.2,7243.76 U19.55@6057.2,7256.3 6057.2,7273.76 6019.47,7311.49 5999.47,7311.49
  Top Layer w10: v3(5885.81,7325.77) cw(c5899.8,7325.77) 5899.8,7339.77 C39.2@5916.02,7339.77 ; R388.2@6034.47,6839.45 6047.09,6839.45 6066.01,6858.38 v3(6066.01,6864.76)
  Bottom Layer w10: v3(5870.73,7074.18) 5904.99,7074.18 ; v3@5886.33,7326.29 ccw(c5886.33,7325.77) v3(5885.81,7325.77) 5885.81,7093.36 ccw(c5904.99,7093.36) 5904.99,7074.18 ; v3(6066.01,6864.76) 6034.03,6864.76 5959.47,6939.32 5959.47,7051.49 5936.78,7074.18 5904.99,7074.18
VDD_SPI: C25.2 C26.2 U19.29 U21.8 | length 220.6
  Top Layer w7.87: U19.29@6277.97,7019.79 6315.49,7019.79 C26.2@6370.56,6964.72 ; C25.2@6370.72,6918.81 6370.56,6918.97 C26.2@6370.56,6964.72 ; U21.8@6386.29,7017.44 6370.56,7001.72 C26.2@6370.56,6964.72
WL_NDIS: CN2.89
pads on no net: CN2.64 CN2.68 CN2.70 CN2.72 CN2.73 CN3.4 CN3.6 CN3.33 CN3.35 CN3.39 CN3.41 CN3.43 CN3.45 CN3.46 CN3.47 CN3.48 CN3.49 CN3.52 CN3.54 CN3.58 CN3.60 CN3.64 CN3.66 CN4.16 CN4.91 FPC2.4 FPC2.15 FPC2.16 U10.8 U10.13 U10.14 U10.15 U10.16 U10.19 U10.27 U19.36 U19.37 U35.1 U35.3 U35.6 U35.10 U38.4 U38.12 U72.3 U72.4 U72.7 U72.10 U72.14 U72.15 U72.16 U83.2 USB1.A8 USB1.B8 USB2.A8 USB2.B8 USB3.17

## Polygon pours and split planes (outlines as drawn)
$3N25641 on Top Layer (solid, remove dead copper, pour order 0): 8163.39,5740.41 8259.47,5836.49 8259.47,5996.49 8179.47,5996.49 8123.93,5940.95 8123.93,5740.41
GND on Bottom Layer (solid, remove dead copper, pour order 36): 8439.71,8216.8 8499.71,8156.8 8499.71,3116.8 3935.01,3125.02 3219.71,4276.8 3219.71,8216.8
VCC3V3_SYS on Top Layer (solid, remove dead copper, pour order 4): 7941.51,5994.71 8012.69,5994.71 8014.47,5996.49 8014.47,5891.49 7900.04,5777.07 7900.04,5721.82 7959.15,5721.82 7964.47,5716.49 7964.47,5608.27 7951.69,5595.48 7909.94,5595.48 7909.94,5600.63 7889.07,5621.49 7608.87,5621.49 7608.87,5687.09 7604.47,5691.49 7759.47,5691.49 7819.47,5751.49 7819.47,5803.21 7941.51,5925.25
$3N11421 on Top Layer (solid, remove dead copper, pour order 6): 4829.47,4035.77 4829.47,4081.49 4914.47,4166.49 4944.47,4166.49 4944.47,4253.96 4935.58,4262.85 4780.06,4262.85 4780.06,4040.9 4785.19,4035.77
$3N11399 on Top Layer (solid, remove dead copper, pour order 8): 4588.72,4218.96 4632,4218.96 4634.47,4216.49 4634.47,4256.49 4644.47,4266.49 4704.47,4266.49 4709.47,4261.49 4709.47,4031.49 4599.47,4031.49 4584.47,4046.49 4584.47,4211.49 4589.47,4216.49 4589.47,4218.21
VCC5V0_USB on Top Layer (solid, remove dead copper, pour order 10): 7384.53,5445.59 7591.84,5445.59 7591.84,5393.86 7584.47,5386.49 7439.47,5386.49 7434.47,5391.49 7391.09,5391.49 7384.52,5398.06 7384.52,5452.79 7384.53,5452.78
+5V_INPUT on Top Layer (solid, remove dead copper, pour order 12): 7034.58,5129.74 7175.37,5129.74 7184.83,5120.29 7314.01,5120.29 7324.79,5109.5 7324.79,5095.09 7343.13,5076.75 7389.73,5076.75 7394.47,5081.49 7394.47,5215.72 7430.24,5251.49 7509.47,5251.49 7509.47,5316.49 7504.47,5321.49 7226.33,5321.49 7034.58,5188.95
$3N24551 on Top Layer (solid, remove dead copper, pour order 14): 7504.47,5201.49 7707.8,5201.49 7735.05,5174.23 7782.22,5174.23 7782.22,5158.73 7607.26,5158.73 7576.71,5128.18 7576.71,5088.73 7569.47,5081.49 7508.11,5081.49 7508.11,5197.85
VBUS on Top Layer (solid, remove dead copper, pour order 16): 7437.03,3348.18 7464.47,3348.18 7464.47,3516.49 7674.47,3726.49 7674.47,3936.49 7664.47,3946.49 7619.99,3946.49 7565.62,4000.86 7525.5,4000.86 7525.5,3722.53 7244.47,3441.49 7244.47,3351.49 7249.47,3346.49 7272.62,3346.49 7272.62,3414.64 7294.47,3436.49 7414.47,3436.49 7434.47,3416.49 7434.47,3411.49 7437.03,3408.93
VBUSI on Top Layer (solid, remove dead copper, pour order 18): 7589.47,4011.49 7674.47,4011.49 7699.47,4036.49 7699.47,4279.17 7778.67,4358.37 7778.67,4477.29 7734.47,4521.49 7647.94,4521.49 7559.47,4433.02 7559.47,4041.49
PCIN on Top Layer (solid, remove dead copper, pour order 20): 7396.5,4369.46 7462.44,4369.46 7489.02,4396.05 7489.02,4656.94 7484.47,4661.49 7395.89,4661.49 7395.89,4370.07
$1N9630 on Top Layer (solid, remove dead copper, pour order 22): 7554.47,4566.49 7569.47,4551.49 7689.47,4551.49 7694.47,4556.49 7694.47,4851.49 7493.45,4851.49 7449.26,4807.3 7449.26,4716.71 7491.51,4674.45 7574.69,4674.45 7574.69,4633.79 7500.75,4633.79 7500.75,4575.21 7509.47,4566.49
LX2 on Top Layer (solid, remove dead copper, pour order 24): 8074.47,4851.49 8074.47,4719.23 8024.47,4669.23 8024.47,4601.49 7979.45,4601.49 7954.47,4576.51 7954.47,4556.49 7835.38,4556.49 7835.38,4851.49
PCON on Top Layer (solid, remove dead copper, pour order 26): 8044.48,4674.79 8306.18,4674.79 8354.47,4626.49 8354.47,4561.53 8040.73,4561.53 8040.73,4671.04
VBUSI on Top Layer (solid, remove dead copper, pour order 28): 8275.12,4193.41 8291.33,4209.62 8321.34,4209.62 8324.47,4206.49 8324.47,4114.12 8286.42,4114.12 8259.05,4141.49 8177.47,4141.49 8177.47,4191.49 8179.39,4193.41
+5V on Top Layer (solid, remove dead copper, pour order 30): 6889.47,5761.49 7094.47,5761.49 7286.38,5569.58 7286.38,5388.41 7152.56,5388.41 7149.47,5391.49 7149.47,5556.49 7034.47,5671.49 6889.47,5671.49
BAT on Top Layer (solid, remove dead copper, pour order 32): 8207.44,4811.96 8354.47,4811.96 8354.47,5121.49 8494.47,5261.49 8494.47,6516.49 8514.47,6536.49 9054.47,6536.49 9084.47,6566.49 9084.47,6656.49 9044.47,6696.49 8344.47,6696.49 8344.47,5770.96 8304.7,5731.19 8124.77,5731.19 8124.47,5731.49 8124.47,5701.49 8129.47,5696.49 8188.16,5696.49 8224.36,5660.29 8224.36,5601.75 8228.9,5597.21 8276.56,5597.21 8276.56,5348.58 8209.47,5281.49 7954.47,5281.49 7869.54,5196.56 7869.54,5159.01 7858.2,5170.35 7808.33,5170.35 7794.47,5156.49 7769.47,5156.49 7764.47,5151.49 7764.47,5139.34 7821.62,5139.34 7838.46,5122.5 7838.46,5032.5 7849.47,5021.49 7869.47,5021.49 7919.47,5071.49 8054.23,5071.49 8124.24,5001.48 8124.24,4895.16
GND on Top Layer (solid, remove dead copper, pour order 34): 8456.07,8213.73 8501.07,8168.73 8501.07,3113.73 3954.89,3121.94 3236.07,4258.73 3236.07,8213.73

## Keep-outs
Top Layer:
  region: 7703.71,4858.97 7830.23,4858.97 7830.23,4543.3 7703.71,4543.3
  region: 7343.13,5070.83 7398.81,5070.83 7399.47,5071.49 7399.47,5216.49 7420.38,5237.41 7493.55,5237.41 7499.47,5231.49 7499.47,5079.78 7508.11,5071.14 7555.73,5071.14 7555.73,5027.75 7554.47,5026.49 7349.32,5026.49 7343.13,5032.68
  region: 7984.47,6031.49 7984.47,6061.49 8009.47,6086.49 8243.17,6086.49 8243.17,6012.68 8240.27,6009.78 8177.76,6009.78 8116.1,5948.12 8116.1,5803.12 8114.47,5801.49 7955.77,5801.49 7955.77,5817.79 8019.47,5881.49 8019.47,5996.49
  region: 4713.13,4272.69 4776.12,4272.69 4776.12,4095.52 4713.65,4095.52 4713.65,4272.17
Board Outline Layer:
  circle w1: c5249.47,7396.49 r59.55
  circle w10: c5249.47,7396.49 r59.55
  circle w1: c7038.33,7395.23 r59.55
  circle w10: c7038.33,7395.23 r59.55
  circle w1: c7825.73,3712.83 r59.55
  circle w10: c7825.73,3712.83 r59.55
  region: 8513.52,6524.13 9172.18,6524.13 9172.18,3728.85 8513.52,3728.85
  region: 3161.75,6524.13 3820.41,6524.13 3820.41,3728.85 3161.75,3728.85
  lines w1: 3161.75,3728.85 3820.41,3728.85 3820.41,6524.13 3161.75,6524.13 3161.75,3728.85 ; 8513.52,3728.85 9172.18,3728.85 9172.18,6524.13 8513.52,6524.13 8513.52,3728.85
  lines w10: 3000.54,3547.93 3684.69,3547.93 ; 3000.86,3549.01 3000.86,3706.49 ; 3000.86,3705.49 3000,6700.55 4768.92,6701.06 ccw(c4768.86,6898.41) 4966.21,6898.41 4966.21,8078.79 7331.99,8078.79 7331.99,6899.2 ccw(c7529.34,6899.2) 7529.4,6701.85 9298.2,6702.36 9299.06,3549.1 8594.51,3549.1 8353.44,3133.24 3932.43,3133.24 3684.45,3549.01 ; 5176.2,7017.6 5177.26,7017.93 5178.34,7018.17 5178.7,7018.27 ; 6916.18,7006.91 6917.24,7007.24 6918.32,7007.48 6918.68,7007.58 ; 3591.91,3705.66 cw(c3591.91,3705.16) 3592.34,3705.41 ; 3591.91,3705.66 cw(c3591.91,3705.16) 3592.34,3705.41 ; 3591.91,3705.66 cw(c3591.91,3705.16) 3592.34,3705.41

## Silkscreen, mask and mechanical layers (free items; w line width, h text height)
Top Silkscreen Layer:
  drawing of 408 lines, arcs and shapes, not listed
Bottom Silkscreen Layer:
  drawing of 646 lines, arcs and shapes, not listed
Mechanical Layer:
  circle w1: c5249.47,7396.49 r59.55
  circle w1: c7038.33,7395.23 r59.55
  circle w1: c7825.73,3712.83 r59.55
  lines w1: 3161.75,3728.85 3820.41,3728.85 3820.41,6524.13 3161.75,6524.13 3161.75,3728.85 ; 8513.52,3728.85 9172.18,3728.85 9172.18,6524.13 8513.52,6524.13 8513.52,3728.85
